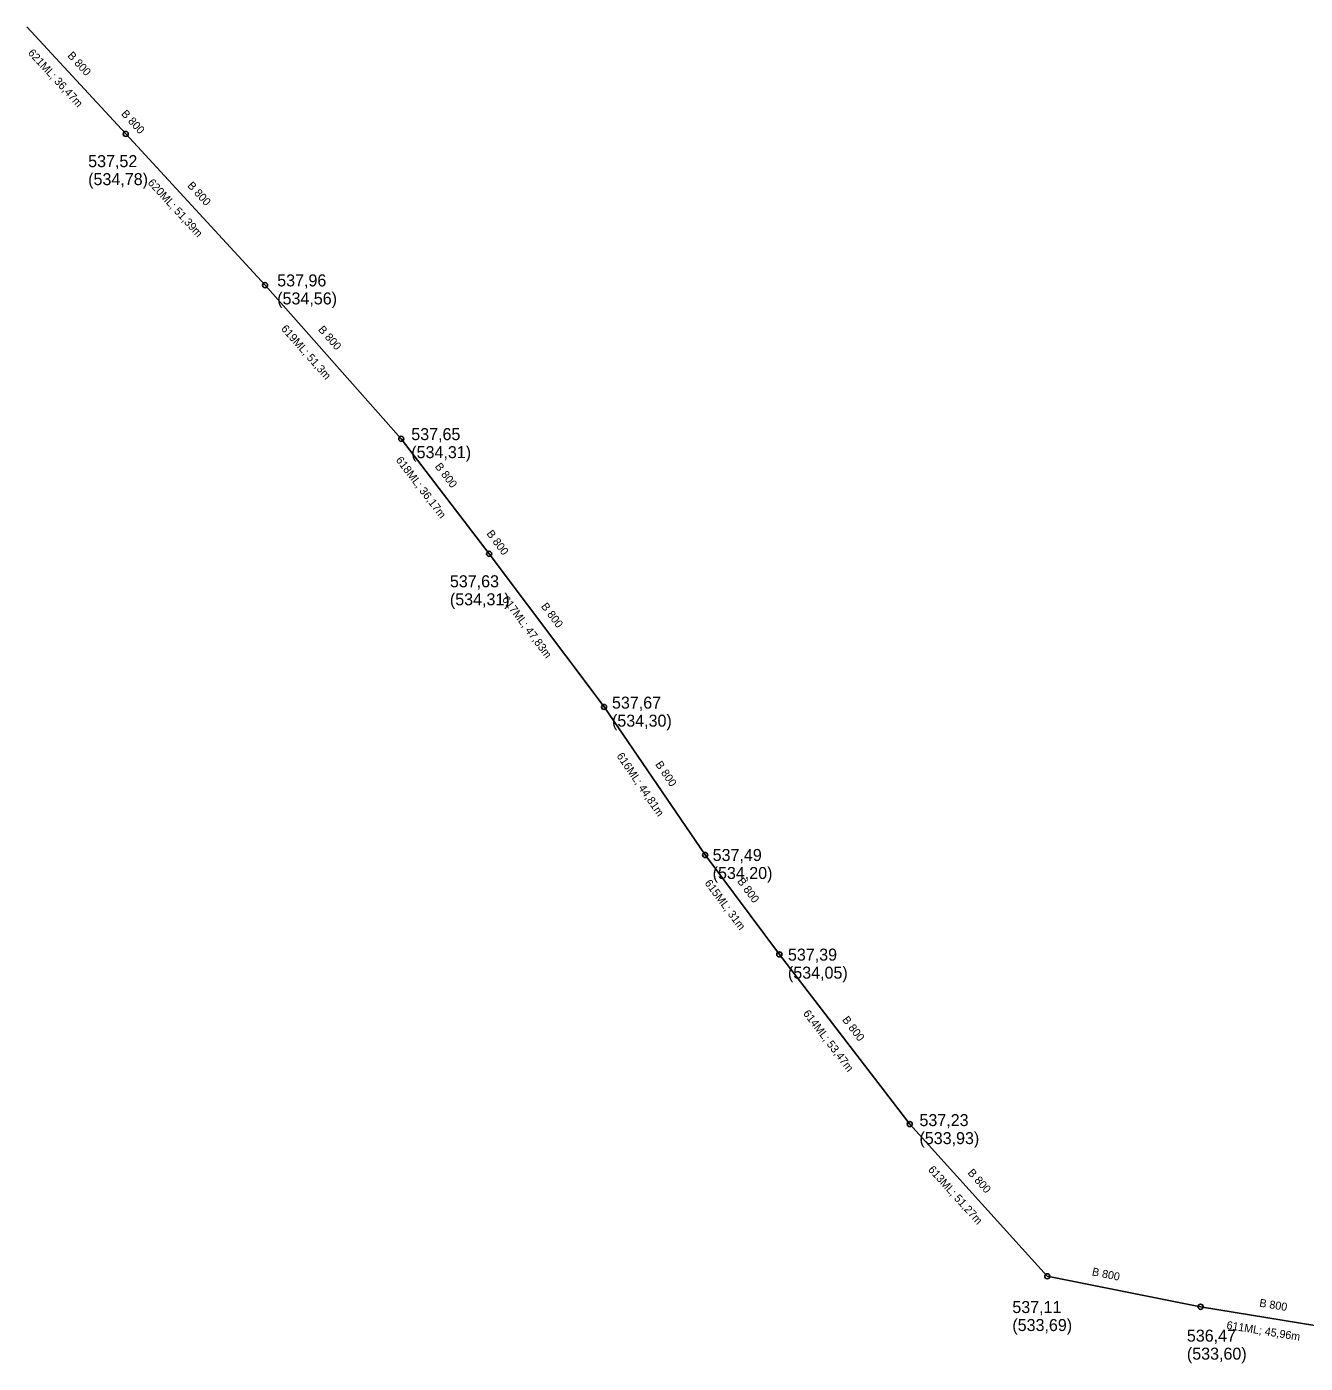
# Model space of a CAD drawing. Extents: x -867696 to -865033, y -1042522 to -1039817.
# Drawn here: x -867695.9 to -867376.4, y -1040301.4 to -1039967.4 of the extents above; entities that cross this region are included whole.
import ezdxf

# ---------------------------------------------------------------- set-up
doc = ezdxf.new("R2010")
doc.units = 0
for name, color, linetype in [('KN - jednotna', 7, 'Continuous'), ('KN - popis material', 7, 'Continuous'), ('KN - popis ostatni', 7, 'Continuous'), ('KN - popis usek delka', 7, 'Continuous'), ('KN - sachta komora', 7, 'Continuous'), ('Level 1', 7, 'Continuous')]:
    doc.layers.add(name, color=color, linetype=linetype)

# ---------------------------------------------------------------- blocks, each defined once
blk = doc.blocks.new('100.M')
at = {"layer": 'Level 1'}
blk.add_circle((0, 0), 1.27, dxfattribs=at)

msp = doc.modelspace()

# ---------------------------------------------------------------- linework, layer by layer
at = {"layer": 'KN - jednotna'}
for points in [[(-867671.128, -1039994.197), (-867695.878, -1039967.407)], [(-867636.309, -1040031.998), (-867671.128, -1039994.197)], [(-867602.288, -1040070.398), (-867636.309, -1040031.998)], [(-867580.308, -1040099.128), (-867602.288, -1040070.398)], [(-867551.597, -1040137.377), (-867580.308, -1040099.128)], [(-867526.339, -1040174.387), (-867551.597, -1040137.377)], [(-867507.798, -1040199.228), (-867526.339, -1040174.387)], [(-867475.208, -1040241.618), (-867507.798, -1040199.228)], [(-867440.848, -1040279.669), (-867475.208, -1040241.618)], [(-867402.519, -1040287.289), (-867440.848, -1040279.669)], [(-867357.159, -1040294.689), (-867402.519, -1040287.289)]]:
    msp.add_lwpolyline(points, dxfattribs=at)

# ---------------------------------------------------------------- block references
at = {"layer": 'KN - sachta komora'}
for p, xscale, yscale, rotation in [((-867671.128, -1039994.197), 0.50000000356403, 0.50000000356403, 133.00000056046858), ((-867636.309, -1040031.998), 0.50000000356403, 0.50000000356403, 133.00000056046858), ((-867602.288, -1040070.398), 0.5000000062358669, 0.5000000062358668, 130.0000013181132), ((-867580.308, -1040099.128), 0.5000000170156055, 0.5000000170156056, 128.00000040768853), ((-867551.597, -1040137.377), 0.5000000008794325, 0.5000000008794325, 125.99999933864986), ((-867526.339, -1040174.387), 0.5000000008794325, 0.5000000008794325, 125.99999933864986), ((-867507.798, -1040199.228), 0.5000000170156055, 0.5000000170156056, 128.00000040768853), ((-867475.208, -1040241.618), 0.5000000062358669, 0.5000000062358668, 130.0000013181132), ((-867440.848, -1040279.669), 0.5018521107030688, 0.5018521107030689, 150.62079160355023), ((-867402.519, -1040287.289), 0.5036654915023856, 0.5036654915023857, 167.86109133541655)]:
    msp.add_blockref('100.M', p, dxfattribs=dict(at, xscale=xscale, yscale=yscale, rotation=rotation))

# ---------------------------------------------------------------- texts
at = {"layer": 'KN - popis material'}
for rotation, p in [(312.73, (-867685.838, -1039974.738)), (312.73, (-867672.419, -1039989.263)), (312.65, (-867655.884, -1040007.205)), (311.54, (-867623.196, -1040043.18)), (307.42, (-867593.979, -1040077.31)), (306.89, (-867581.089, -1040094.088)), (306.89, (-867567.459, -1040112.247)), (304.31, (-867538.888, -1040151.742)), (306.74, (-867518.43, -1040180.971)), (307.55, (-867492.191, -1040215.589)), (312.08, (-867460.878, -1040253.906)), (348.76, (-867429.778, -1040279.424)), (350.73, (-867387.945, -1040287.234))]:
    msp.add_text('B 800', height=2, rotation=rotation, dxfattribs=at).set_placement(p)
at = {"layer": 'KN - popis ostatni'}
for s, p in [('537,52 ', (-867680.518, -1040002.497)), ('(534,78)', (-867680.518, -1040006.997)), ('537,96 ', (-867633.279, -1040032.298)), ('(534,56)', (-867633.279, -1040036.798)), ('537,65 ', (-867599.778, -1040070.718)), ('(534,31)', (-867599.778, -1040075.218)), ('537,63 ', (-867590.128, -1040107.488)), ('(534,31)', (-867590.128, -1040111.988)), ('537,67 ', (-867549.617, -1040137.817)), ('(534,30)', (-867549.617, -1040142.317)), ('537,49 ', (-867524.459, -1040175.887)), ('(534,20)', (-867524.459, -1040180.387)), ('537,39 ', (-867505.648, -1040200.788)), ('(534,05)', (-867505.648, -1040205.288)), ('537,23 ', (-867472.778, -1040242.138)), ('(533,93)', (-867472.778, -1040246.638)), ('537,11 ', (-867449.568, -1040288.849)), ('(533,69)', (-867449.568, -1040293.349)), ('536,47 ', (-867405.949, -1040295.999)), ('(533,60)', (-867405.949, -1040300.499))]:
    msp.add_text(s, height=3, dxfattribs=at).set_placement(p)
at = {"layer": 'KN - popis usek delka'}
for s, height, rotation, p in [('621ML; 36,47m', 1.99999, 312.73, (-867695.718, -1039974.063)), ('620ML; 51,39m', 1.99999, 312.65, (-867665.763, -1040006.517)), ('619ML; 51,3m', 1.99999, 311.54, (-867632.463, -1040042.974)), ('618ML; 36,17m', 1.99999, 307.42, (-867603.755, -1040075.723)), ('617ML; 47,83m', 1.99999, 306.89, (-867577.22, -1040110.571)), ('616ML; 44,81m', 1.99999, 304.31, (-867548.563, -1040149.628)), ('615ML; 31m', 2, 306.74, (-867526.572, -1040181.432)), ('614ML; 53,47m', 1.99999, 307.55, (-867501.971, -1040214.025)), ('613ML; 51,27m', 1.99999, 312.08, (-867470.75, -1040253.12)), ('611ML; 45,96m', 1.99999, 350.73, (-867396.146, -1040292.786))]:
    msp.add_text(s, height=height, rotation=rotation, dxfattribs=at).set_placement(p)

doc.saveas('drawing.dxf')
